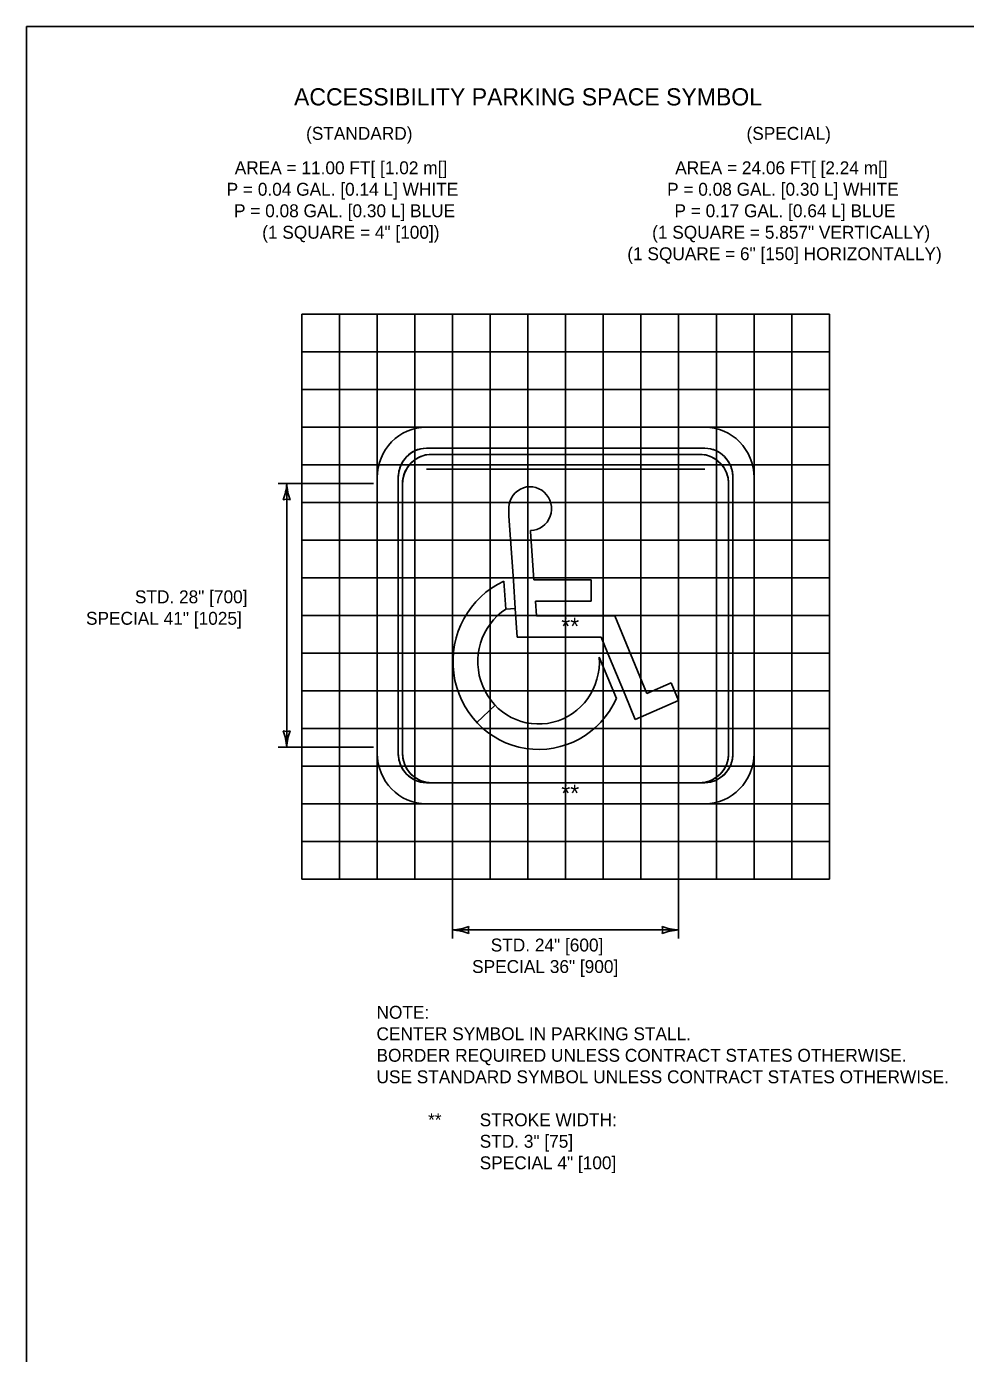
# Model space of a CAD drawing. Extents: x 49948.7 to 50021, y 49977 to 50017.6.
# Drawn here: x 49999.38 to 50003.75, y 49992.83 to 49999 of the extents above; entities that cross this region are included whole.
import ezdxf

# ---------------------------------------------------------------- set-up
doc = ezdxf.new("R2010")
doc.units = 0
for name, color, linetype in [('Level 1', 7, 'Continuous'), ('Level 2', 7, 'Continuous'), ('Level 3', 7, 'Continuous'), ('Level 9', 7, 'Continuous')]:
    doc.layers.add(name, color=color, linetype=linetype)

msp = doc.modelspace()

# ---------------------------------------------------------------- linework, layer by layer
at = {"layer": 'Level 1'}
for p, q in [((50001.2431, 49997.136), (50002.5366, 49997.136)), ((50001.2431, 49997.0379), (50002.5366, 49997.0379)), ((50001.3642, 49997.0379), (50001.2431, 49997.0379)), ((50001.5394, 49997.0379), (50001.3642, 49997.0379)), ((50001.7146, 49997.0379), (50001.5394, 49997.0379)), ((50001.8899, 49997.0379), (50001.7146, 49997.0379)), ((50002.0651, 49997.0379), (50001.8899, 49997.0379)), ((50002.2403, 49997.0379), (50002.0651, 49997.0379)), ((50002.4155, 49997.0379), (50002.2403, 49997.0379)), ((50002.5366, 49997.0379), (50002.4155, 49997.0379)), ((50001.0137, 49996.9005), (50001.0137, 49995.6192)), ((50001.1118, 49996.9005), (50001.1118, 49995.6192)), ((50001.1118, 49996.9005), (50001.1118, 49996.7855)), ((50001.2431, 49996.9398), (50002.5366, 49996.9398)), ((50002.6679, 49996.9005), (50002.6679, 49995.6192)), ((50002.6679, 49996.7855), (50002.6679, 49996.9005)), ((50002.766, 49996.9005), (50002.766, 49995.6192)), ((50001.1118, 49996.7855), (50001.1118, 49996.6103)), ((50002.6679, 49996.6103), (50002.6679, 49996.7855)), ((50001.6266, 49996.7224), (50001.6255, 49996.7474)), ((50001.647, 49996.4221), (50001.6266, 49996.7224)), ((50001.7272, 49996.6543), (50001.7273, 49996.6503)), ((50001.7273, 49996.6503), (50001.7426, 49996.4251)), ((50001.1118, 49996.6103), (50001.1118, 49996.4351)), ((50002.6679, 49996.4351), (50002.6679, 49996.6103)), ((50001.1118, 49996.4351), (50001.1118, 49996.2599)), ((50001.6033, 49996.4189), (50001.6122, 49996.2896)), ((50001.6559, 49996.2928), (50001.647, 49996.4221)), ((50001.7426, 49996.4251), (50002.0081, 49996.4251)), ((50002.0081, 49996.4251), (50002.0081, 49996.327)), ((50002.6679, 49996.2599), (50002.6679, 49996.4351)), ((50002.0081, 49996.327), (50001.7493, 49996.327)), ((50001.7493, 49996.327), (50001.754, 49996.2577)), ((50001.6559, 49996.2927), (50001.6121, 49996.2896)), ((50001.6122, 49996.2896), (50001.6559, 49996.2928)), ((50001.6649, 49996.1595), (50001.6559, 49996.2927)), ((50001.1118, 49996.2599), (50001.1118, 49996.0846)), ((50001.754, 49996.2577), (50002.1185, 49996.2577)), ((50002.1185, 49996.2577), (50002.2677, 49995.8968)), ((50002.6679, 49996.0846), (50002.6679, 49996.2599)), ((50002.0552, 49996.1595), (50001.6649, 49996.1595)), ((50002.0868, 49996.083), (50002.0552, 49996.1595)), ((50001.1118, 49996.0846), (50001.1118, 49995.9094)), ((50002.1662, 49995.891), (50002.0868, 49996.083)), ((50002.6679, 49995.9094), (50002.6679, 49996.0846)), ((50002.0465, 49996.0655), (50002.1259, 49995.8734)), ((50001.1118, 49995.9094), (50001.1118, 49995.7342)), ((50002.2677, 49995.8968), (50002.3813, 49995.9463)), ((50002.3813, 49995.9463), (50002.4155, 49995.8635)), ((50002.6679, 49995.7342), (50002.6679, 49995.9094)), ((50002.2139, 49995.7757), (50002.1662, 49995.891)), ((50002.4155, 49995.8635), (50002.2139, 49995.7757)), ((50001.1118, 49995.7342), (50001.1118, 49995.6192)), ((50002.6679, 49995.6192), (50002.6679, 49995.7342)), ((50001.2431, 49995.4818), (50002.5366, 49995.4818)), ((50001.2431, 49995.4818), (50001.2655, 49995.4818)), ((50001.2655, 49995.4818), (50001.2655, 49995.4818)), ((50001.2655, 49995.4818), (50002.5142, 49995.4818)), ((50002.5142, 49995.4818), (50002.5142, 49995.4818)), ((50002.5142, 49995.4818), (50002.5366, 49995.4818)), ((50001.2431, 49995.3837), (50002.5366, 49995.3837))]:
    msp.add_line(p, q, dxfattribs=at)
msp.add_lwpolyline([(49999.3835, 49998.9992), (50016.7501, 49998.9992), (50016.7501, 49987.7988), (49999.3835, 49987.7988)], close=True, dxfattribs=at)
for centre, major_axis, ratio, start_param, end_param in [((50001.2431, 49996.9005), (0, 0.2355), 0.974025, 0, 1.570796), ((50002.5366, 49996.9005), (0, 0.2355), 0.974025, 4.712389, 6.283185), ((50001.2431, 49996.9005), (0, 0.1374), 0.95548, 0, 1.570796), ((50001.2431, 49996.9005), (0, 0.1374), 0.95548, 0, 1.570796), ((50002.5366, 49996.9005), (0, 0.1374), 0.95548, 4.712389, 6.283185), ((50002.5366, 49996.9005), (0, 0.1374), 0.95548, 4.712389, 6.283185), ((50001.7247, 49996.7565), (0, 0.1022), 0.974025, 3.16664, 7.943174), ((50001.7645, 49996.0451), (0, 0.4089), 0.974025, 0.416757, 4.279079), ((50001.7645, 49996.0451), (0, -0.2903), 0.974025, 3.71076, 7.92435), ((50001.2431, 49995.6192), (0, -0.2355), 0.974025, 4.712389, 6.283185), ((50001.2431, 49995.6192), (0, -0.1374), 0.95548, 4.712389, 6.283185), ((50001.2431, 49995.6192), (0, -0.1374), 0.95548, 4.712389, 6.283185), ((50002.5366, 49995.6192), (0, -0.2355), 0.974025, 0, 1.570796), ((50002.5366, 49995.6192), (0, -0.1374), 0.95548, 0, 1.570796), ((50002.5366, 49995.6192), (0, -0.1374), 0.95548, 0, 1.570796)]:
    msp.add_ellipse(centre, major_axis=major_axis, ratio=ratio, start_param=start_param, end_param=end_param, dxfattribs=at)
at = {"layer": 'Level 3'}
for p, q in [((50001.189, 49997.0257), (50001.189, 49996.9842)), ((50001.189, 49996.9842), (50001.189, 49997.0257)), ((50001.3642, 49997.0379), (50001.2431, 49997.0379)), ((50002.5142, 49997.009), (50001.2655, 49997.009)), ((50001.2655, 49997.009), (50001.3642, 49997.009)), ((50001.3642, 49997.009), (50001.3642, 49997.0379)), ((50001.3642, 49997.0379), (50001.3642, 49997.009)), ((50001.5394, 49997.0379), (50001.3642, 49997.0379)), ((50001.3642, 49997.009), (50001.5394, 49997.009)), ((50001.5394, 49997.009), (50001.5394, 49997.0379)), ((50001.5394, 49997.0379), (50001.5394, 49997.009)), ((50001.7146, 49997.0379), (50001.5394, 49997.0379)), ((50001.5394, 49997.009), (50001.7146, 49997.009)), ((50001.7146, 49997.009), (50001.7146, 49997.0379)), ((50001.7146, 49997.0379), (50001.7146, 49997.009)), ((50001.8899, 49997.0379), (50001.7146, 49997.0379)), ((50001.7146, 49997.009), (50001.8899, 49997.009)), ((50001.8899, 49997.009), (50001.8899, 49997.0379)), ((50001.8899, 49997.0379), (50001.8899, 49997.009)), ((50002.0651, 49997.0379), (50001.8899, 49997.0379)), ((50001.8899, 49997.009), (50002.0651, 49997.009)), ((50002.0651, 49997.009), (50002.0651, 49997.0379)), ((50002.0651, 49997.0379), (50002.0651, 49997.009)), ((50002.2403, 49997.0379), (50002.0651, 49997.0379)), ((50002.0651, 49997.009), (50002.2403, 49997.009)), ((50002.2403, 49997.009), (50002.2403, 49997.0379)), ((50002.2403, 49997.0379), (50002.2403, 49997.009)), ((50002.4155, 49997.0379), (50002.2403, 49997.0379)), ((50002.2403, 49997.009), (50002.4155, 49997.009)), ((50002.4155, 49997.009), (50002.4155, 49997.0379)), ((50002.5366, 49997.0379), (50002.4155, 49997.0379)), ((50002.4155, 49997.0379), (50002.4155, 49997.009)), ((50002.4155, 49997.009), (50002.5142, 49997.009)), ((50002.5908, 49996.9842), (50002.5908, 49997.0257)), ((50002.5908, 49997.0257), (50002.5908, 49996.9842)), ((50001.1637, 49996.9608), (50001.1251, 49996.9608)), ((50001.1251, 49996.9608), (50001.1637, 49996.9608)), ((50002.616, 49996.9608), (50002.5908, 49996.9608)), ((50002.5908, 49996.9608), (50002.5908, 49996.7855)), ((50002.616, 49996.9608), (50002.6546, 49996.9608)), ((50002.6546, 49996.9608), (50002.616, 49996.9608)), ((50001.1118, 49996.9005), (50001.1118, 49996.7855)), ((50002.6679, 49996.7855), (50002.6679, 49996.9005)), ((50000.9961, 49996.8739), (50000.5531, 49996.8739)), ((50000.5931, 49996.8739), (50000.5931, 49995.6473)), ((50001.1317, 49996.8716), (50001.1317, 49995.6192)), ((50001.1317, 49996.7855), (50001.1317, 49996.8716)), ((50002.648, 49995.6192), (50002.648, 49996.8716)), ((50002.648, 49996.7855), (50002.648, 49996.8716)), ((50002.648, 49996.8716), (50002.648, 49996.7855)), ((50001.1317, 49996.7855), (50001.1118, 49996.7855)), ((50001.1118, 49996.7855), (50001.1118, 49996.6103)), ((50001.1118, 49996.7855), (50001.1317, 49996.7855)), ((50001.1317, 49996.6103), (50001.1317, 49996.7855)), ((50002.5908, 49996.7855), (50002.648, 49996.7855)), ((50002.648, 49996.7855), (50002.5908, 49996.7855)), ((50002.5908, 49996.7855), (50002.5908, 49996.6103)), ((50002.648, 49996.7855), (50002.5908, 49996.7855)), ((50002.5908, 49996.7855), (50002.5908, 49996.6103)), ((50002.648, 49996.7855), (50002.5908, 49996.7855)), ((50002.5908, 49996.7855), (50002.5908, 49996.6103)), ((50002.648, 49996.7855), (50002.6679, 49996.7855)), ((50002.648, 49996.6103), (50002.648, 49996.7855)), ((50002.648, 49996.6103), (50002.648, 49996.7855)), ((50002.648, 49996.6103), (50002.648, 49996.7855)), ((50002.6679, 49996.7855), (50002.648, 49996.7855)), ((50002.648, 49996.7855), (50002.648, 49996.6103)), ((50002.6679, 49996.6103), (50002.6679, 49996.7855)), ((50001.6266, 49996.7224), (50001.6255, 49996.7474)), ((50001.647, 49996.4221), (50001.6266, 49996.7224)), ((50001.7272, 49996.6543), (50001.7273, 49996.6503)), ((50001.7273, 49996.6503), (50001.7426, 49996.4251)), ((50001.1317, 49996.6103), (50001.1118, 49996.6103)), ((50001.1118, 49996.6103), (50001.1118, 49996.4351)), ((50001.1118, 49996.6103), (50001.1317, 49996.6103)), ((50001.1317, 49996.4351), (50001.1317, 49996.6103)), ((50002.5908, 49996.6103), (50002.648, 49996.6103)), ((50002.5908, 49996.6103), (50002.648, 49996.6103)), ((50002.5908, 49996.6103), (50002.648, 49996.6103)), ((50002.648, 49996.6103), (50002.6679, 49996.6103)), ((50002.6679, 49996.6103), (50002.648, 49996.6103)), ((50002.648, 49996.6103), (50002.648, 49996.4351)), ((50002.6679, 49996.4351), (50002.6679, 49996.6103)), ((50001.1317, 49996.4351), (50001.1118, 49996.4351)), ((50001.1118, 49996.4351), (50001.1118, 49996.2599)), ((50001.1118, 49996.4351), (50001.1317, 49996.4351)), ((50001.1317, 49996.2599), (50001.1317, 49996.4351)), ((50001.6033, 49996.4189), (50001.6122, 49996.2896)), ((50001.6559, 49996.2928), (50001.647, 49996.4221)), ((50001.7426, 49996.4251), (50002.0081, 49996.4251)), ((50002.0081, 49996.4251), (50002.0081, 49996.327)), ((50002.648, 49996.4351), (50002.6679, 49996.4351)), ((50002.6679, 49996.4351), (50002.648, 49996.4351)), ((50002.648, 49996.4351), (50002.648, 49996.2599)), ((50002.6679, 49996.2599), (50002.6679, 49996.4351)), ((50002.0081, 49996.327), (50001.7493, 49996.327)), ((50001.7493, 49996.327), (50001.754, 49996.2577)), ((50001.6559, 49996.2927), (50001.6121, 49996.2896)), ((50001.6122, 49996.2896), (50001.6559, 49996.2928)), ((50001.6649, 49996.1595), (50001.6559, 49996.2927)), ((50001.1317, 49996.2599), (50001.1118, 49996.2599)), ((50001.1118, 49996.2599), (50001.1118, 49996.0846)), ((50001.1118, 49996.2599), (50001.1317, 49996.2599)), ((50001.1317, 49996.0846), (50001.1317, 49996.2599)), ((50001.754, 49996.2577), (50002.1185, 49996.2577)), ((50002.1185, 49996.2577), (50002.2677, 49995.8968)), ((50002.648, 49996.2599), (50002.6679, 49996.2599)), ((50002.6679, 49996.2599), (50002.648, 49996.2599)), ((50002.648, 49996.2599), (50002.648, 49996.0846)), ((50002.6679, 49996.0846), (50002.6679, 49996.2599)), ((50002.0552, 49996.1595), (50001.6649, 49996.1595)), ((50002.0868, 49996.083), (50002.0552, 49996.1595)), ((50001.1317, 49996.0846), (50001.1118, 49996.0846)), ((50001.1118, 49996.0846), (50001.1118, 49995.9094)), ((50001.1118, 49996.0846), (50001.1317, 49996.0846)), ((50001.1317, 49995.9094), (50001.1317, 49996.0846)), ((50002.1662, 49995.891), (50002.0868, 49996.083)), ((50002.648, 49996.0846), (50002.6679, 49996.0846)), ((50002.6679, 49996.0846), (50002.648, 49996.0846)), ((50002.648, 49996.0846), (50002.648, 49995.9094)), ((50002.6679, 49995.9094), (50002.6679, 49996.0846)), ((50002.0465, 49996.0655), (50002.1259, 49995.8734)), ((50001.1317, 49995.9094), (50001.1118, 49995.9094)), ((50001.1118, 49995.9094), (50001.1118, 49995.7342)), ((50001.1118, 49995.9094), (50001.1317, 49995.9094)), ((50001.1317, 49995.7342), (50001.1317, 49995.9094)), ((50002.2677, 49995.8968), (50002.3813, 49995.9463)), ((50002.3813, 49995.9463), (50002.4155, 49995.8635)), ((50002.648, 49995.9094), (50002.6679, 49995.9094)), ((50002.6679, 49995.9094), (50002.648, 49995.9094)), ((50002.648, 49995.9094), (50002.648, 49995.7342)), ((50002.6679, 49995.7342), (50002.6679, 49995.9094)), ((50001.5621, 49995.8423), (50001.4774, 49995.7617)), ((50002.2139, 49995.7757), (50002.1662, 49995.891)), ((50002.4155, 49995.8635), (50002.2139, 49995.7757)), ((50001.1317, 49995.7342), (50001.1118, 49995.7342)), ((50001.1118, 49995.7342), (50001.1118, 49995.6192)), ((50001.1118, 49995.7342), (50001.1317, 49995.7342)), ((50001.1317, 49995.6192), (50001.1317, 49995.7342)), ((50002.648, 49995.7342), (50002.6679, 49995.7342)), ((50002.6679, 49995.7342), (50002.648, 49995.7342)), ((50002.648, 49995.7342), (50002.648, 49995.6192)), ((50002.6679, 49995.6192), (50002.6679, 49995.7342)), ((50000.9961, 49995.6473), (50000.5531, 49995.6473)), ((50001.1453, 49995.5589), (50001.1251, 49995.5589)), ((50001.1251, 49995.5589), (50001.1453, 49995.5589)), ((50002.6344, 49995.5589), (50002.6546, 49995.5589)), ((50002.6546, 49995.5589), (50002.6344, 49995.5589)), ((50001.189, 49995.4941), (50001.189, 49995.5066)), ((50001.189, 49995.5066), (50001.189, 49995.4941)), ((50001.2431, 49995.4818), (50001.2655, 49995.4818)), ((50001.2655, 49995.4818), (50002.5142, 49995.4818)), ((50002.5142, 49995.4818), (50002.5366, 49995.4818)), ((50002.5908, 49995.5066), (50002.5908, 49995.4941)), ((50002.5908, 49995.4941), (50002.5908, 49995.5066)), ((50001.3642, 49995.3437), (50001.3638, 49994.7567)), ((50002.4155, 49995.3437), (50002.4152, 49994.7567)), ((50001.3639, 49994.7967), (50002.4153, 49994.7967)), ((50001.3639, 49994.7967), (50002.4153, 49994.7967))]:
    msp.add_line(p, q, dxfattribs=at)
for points in [[(50001.2655, 49995.4818), (50001.2655, 49995.4818)], [(50002.5142, 49995.4818), (50002.5142, 49995.4818)]]:
    msp.add_lwpolyline(points, dxfattribs=at)
for centre, radius, start, end in [((50000.371, 49996.8831), 0.2223, 337.45601, 357.63952), ((50000.8258, 49996.8854), 0.233, 182.82731, 202.07716), ((50000.5931, 49996.7457), 0.0548, 72.13882, 107.86118), ((50000.5931, 49995.7755), 0.0548, 252.13882, 287.86118), ((50000.3604, 49995.6358), 0.233, 2.82731, 22.07716), ((50000.8152, 49995.6381), 0.2223, 157.45601, 177.63952), ((50001.3524, 49995.0294), 0.233, 272.82731, 292.07716), ((50001.3547, 49994.5746), 0.2223, 67.45601, 87.63952), ((50001.4921, 49994.7967), 0.0548, 162.13882, 197.86118), ((50002.4244, 49995.0188), 0.2223, 247.45601, 267.63952), ((50002.287, 49994.7967), 0.0548, 342.13882, 17.86118), ((50002.4268, 49994.564), 0.233, 92.82731, 112.07716)]:
    msp.add_arc(centre, radius, start, end, dxfattribs=at)
for centre, major_axis, ratio, start_param, end_param in [((50001.2431, 49996.9005), (0, 0.1374), 0.95548, 0.425236, 1.116657), ((50001.2655, 49996.8716), (0, 0.1374), 0.974025, 0, 1.570796), ((50001.2431, 49996.9005), (0, 0.1374), 0.95548, 0, 0.425236), ((50001.2655, 49996.8716), (0, 0.1374), 0.974025, 0, 0.609156), ((50002.5142, 49996.8716), (0, 0.1374), 0.974025, 4.712389, 6.283185), ((50002.5142, 49996.8716), (0, 0.1374), 0.974025, 5.674038, 6.283185), ((50002.5366, 49996.9005), (0, 0.1374), 0.95548, 5.857949, 6.283185), ((50002.5366, 49996.9005), (0, 0.1374), 0.95548, 5.166529, 5.857949), ((50001.2431, 49996.9005), (0, 0.1374), 0.95548, 1.116657, 1.570796), ((50001.2655, 49996.8716), (0, 0.1374), 0.974025, 0.864311, 1.570796), ((50001.2655, 49996.8716), (0, 0.1374), 0.974025, 0.609156, 0.864311), ((50002.5142, 49996.8716), (0, 0.1374), 0.974025, 5.418874, 5.674038), ((50002.5142, 49996.8716), (0, 0.1374), 0.974025, 4.712389, 5.418874), ((50002.5142, 49996.8716), (0, 0.1374), 0.974025, 4.712389, 5.418874), ((50002.5366, 49996.9005), (0, 0.1374), 0.95548, 4.712389, 5.166529), ((50001.7247, 49996.7565), (0, 0.1022), 0.974025, 3.16664, 7.943174), ((50001.7645, 49996.0451), (0, 0.4089), 0.974025, 0.416757, 4.279079), ((50001.7645, 49996.0451), (0, -0.2903), 0.974025, 3.71076, 7.92435), ((50001.2431, 49995.6192), (0, -0.1374), 0.95548, 4.712389, 5.166529), ((50001.2655, 49995.6192), (0, -0.1374), 0.974025, 4.712389, 6.283185), ((50001.2655, 49995.6192), (0, -0.1374), 0.974025, 4.712389, 5.166624), ((50002.5142, 49995.6192), (0, -0.1374), 0.974025, 0, 1.570796), ((50002.5142, 49995.6192), (0, -0.1374), 0.974025, 1.116561, 1.570796), ((50002.5366, 49995.6192), (0, -0.1374), 0.95548, 1.116657, 1.570796), ((50001.2431, 49995.6192), (0, -0.1374), 0.95548, 5.166529, 5.857949), ((50001.2655, 49995.6192), (0, -0.1374), 0.974025, 5.166624, 5.674029), ((50002.5142, 49995.6192), (0, -0.1374), 0.974025, 0.609147, 1.116561), ((50002.5366, 49995.6192), (0, -0.1374), 0.95548, 0.425236, 1.116657), ((50001.2655, 49995.6192), (0, -0.1374), 0.974025, 5.674029, 6.283185), ((50001.2431, 49995.6192), (0, -0.1374), 0.95548, 5.857949, 6.283185), ((50002.5142, 49995.6192), (0, -0.1374), 0.974025, 0, 0.609147), ((50002.5366, 49995.6192), (0, -0.1374), 0.95548, 0, 0.425236)]:
    msp.add_ellipse(centre, major_axis=major_axis, ratio=ratio, start_param=start_param, end_param=end_param, dxfattribs=at)
at = {"layer": 'Level 9'}
for p, q in [((50000.6633, 49997.6617), (50003.1164, 49997.6617)), ((50000.6633, 49997.6617), (50000.6633, 49995.0333)), ((50000.8385, 49997.6617), (50000.8385, 49995.0333)), ((50001.0137, 49997.6617), (50001.0137, 49995.0333)), ((50001.189, 49997.6617), (50001.189, 49995.0333)), ((50001.3642, 49997.6617), (50001.3642, 49995.0333)), ((50001.5394, 49997.6617), (50001.5394, 49995.0333)), ((50001.7146, 49997.6617), (50001.7146, 49995.0333)), ((50001.8899, 49997.6617), (50001.8899, 49995.0333)), ((50002.0651, 49997.6617), (50002.0651, 49995.0333)), ((50002.2403, 49997.6617), (50002.2403, 49995.0333)), ((50002.4155, 49997.6617), (50002.4155, 49995.0333)), ((50002.5908, 49997.6617), (50002.5908, 49995.0333)), ((50002.766, 49997.6617), (50002.766, 49995.0333)), ((50002.9412, 49997.6617), (50002.9412, 49995.0333)), ((50003.1164, 49997.6617), (50003.1164, 49995.0333)), ((50000.6633, 49997.4864), (50003.1164, 49997.4864)), ((50000.6633, 49997.3112), (50003.1164, 49997.3112)), ((50000.6633, 49997.136), (50003.1164, 49997.136)), ((50000.6633, 49996.9608), (50003.1164, 49996.9608)), ((50000.6633, 49996.7855), (50003.1164, 49996.7855)), ((50000.6633, 49996.6103), (50003.1164, 49996.6103)), ((50000.6633, 49996.4351), (50003.1164, 49996.4351)), ((50000.6633, 49996.2599), (50003.1164, 49996.2599)), ((50000.6633, 49996.0846), (50003.1164, 49996.0846)), ((50000.6633, 49995.9094), (50003.1164, 49995.9094)), ((50000.6633, 49995.7342), (50003.1164, 49995.7342)), ((50000.6633, 49995.5589), (50003.1164, 49995.5589)), ((50000.6633, 49995.3837), (50003.1164, 49995.3837)), ((50000.6633, 49995.2085), (50003.1164, 49995.2085)), ((50000.6633, 49995.0333), (50003.1164, 49995.0333))]:
    msp.add_line(p, q, dxfattribs=at)

# ---------------------------------------------------------------- texts
at = {"layer": 'Level 2'}
for s, height, p in [('ACCESSIBILITY PARKING SPACE SYMBOL', 0.08, (50000.6272, 49998.6322)), ('(STANDARD)', 0.06, (50000.6832, 49998.4722)), ('(SPECIAL)', 0.06, (50002.7311, 49998.4722)), ('AREA = 11.00 FT[ [1.02 m[]', 0.06, (50000.3516, 49998.3122)), ('AREA = 24.06 FT[ [2.24 m[]', 0.06, (50002.3996, 49998.3122)), ('P = 0.04 GAL. [0.14 L] WHITE', 0.06, (50000.3138, 49998.2122)), ('P = 0.08 GAL. [0.30 L] WHITE', 0.06, (50002.3618, 49998.2122)), ('P = 0.08 GAL. [0.30 L] BLUE', 0.06, (50000.3481, 49998.1122)), ('P = 0.17 GAL. [0.64 L] BLUE', 0.06, (50002.396, 49998.1122)), ('(1 SQUARE = 4" [100])', 0.06, (50000.4792, 49998.0122)), ('(1 SQUARE = 5.857" VERTICALLY)', 0.06, (50002.2922, 49998.0122)), ('(1 SQUARE = 6" [150] HORIZONTALLY)', 0.06, (50002.1768, 49997.9122)), ('STD. 28" [700]', 0.06, (49999.8874, 49996.3165)), ('SPECIAL 41" [1025]', 0.06, (49999.66, 49996.2165)), ('**', 0.08, (50001.8698, 49996.1698)), ('**', 0.08, (50001.8698, 49995.3932)), ('STD. 24" [600]', 0.06, (50001.5419, 49994.6967)), ('SPECIAL 36" [900]', 0.06, (50001.4552, 49994.5967)), ('NOTE: ', 0.06, (50001.0106, 49994.3838)), ('CENTER SYMBOL IN PARKING STALL. ', 0.06, (50001.0106, 49994.2838)), ('BORDER REQUIRED UNLESS CONTRACT STATES OTHERWISE.', 0.06, (50001.0106, 49994.1838)), ('USE STANDARD SYMBOL UNLESS CONTRACT STATES OTHERWISE.', 0.06, (50001.0106, 49994.0838)), ('** ', 0.06, (50001.2506, 49993.8838)), ('STROKE WIDTH:', 0.06, (50001.4906, 49993.8838)), ('STD. 3" [75]', 0.06, (50001.4906, 49993.7838)), ('SPECIAL 4" [100]', 0.06, (50001.4906, 49993.6838))]:
    msp.add_text(s, height=height, dxfattribs=at).set_placement(p)

doc.saveas('drawing.dxf')
